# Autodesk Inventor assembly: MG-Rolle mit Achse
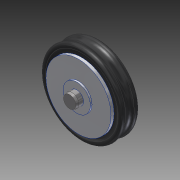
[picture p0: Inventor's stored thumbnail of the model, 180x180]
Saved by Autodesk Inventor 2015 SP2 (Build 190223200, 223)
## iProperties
Created: 2012-07
Part Number: MG-Rolle mit Achse
Document SubType Name: Assembly
Designer: rYan
Mass: 0.768817 g
Surface Area: 6.39688 cm^2
Volume: 0.302245 cm^3
Density: 2.54369 g/cm^3
Author: rYan
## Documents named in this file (4)
- E:\TIGERs GIT\Hardware\mechanik\2016\Inventor\Antrieb\MG-Rolle mit Achse.iam
- E:\TIGERs GIT\Hardware\mechanik\2016\Inventor\Antrieb\Rolle.ipt
- E:\TIGERs GIT\Hardware\mechanik\2016\Inventor\Kaufteile\X-Ring 6x2.6.ipt
- E:\TIGERs GIT\Hardware\mechanik\2016\Inventor\Inhaltscenter\de-DE\ISO 2338(1)\ISO 2338 - 2 m6 x 6DIN EN.ipt
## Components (3 placed, 3 different names)
1. Rolle:1 — Passend:2, Passend:3
2. DIN EN ISO 2338 2 m6 x 6:1
3. X-Ring 6x2.6:1 — Passend:2, Passend:3
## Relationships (2: Mate 2)
- Passend:2 [Mate]: Rolle:1 ↔ X-Ring 6x2.6:1
- Passend:3 [Mate]: Rolle:1 ↔ X-Ring 6x2.6:1
